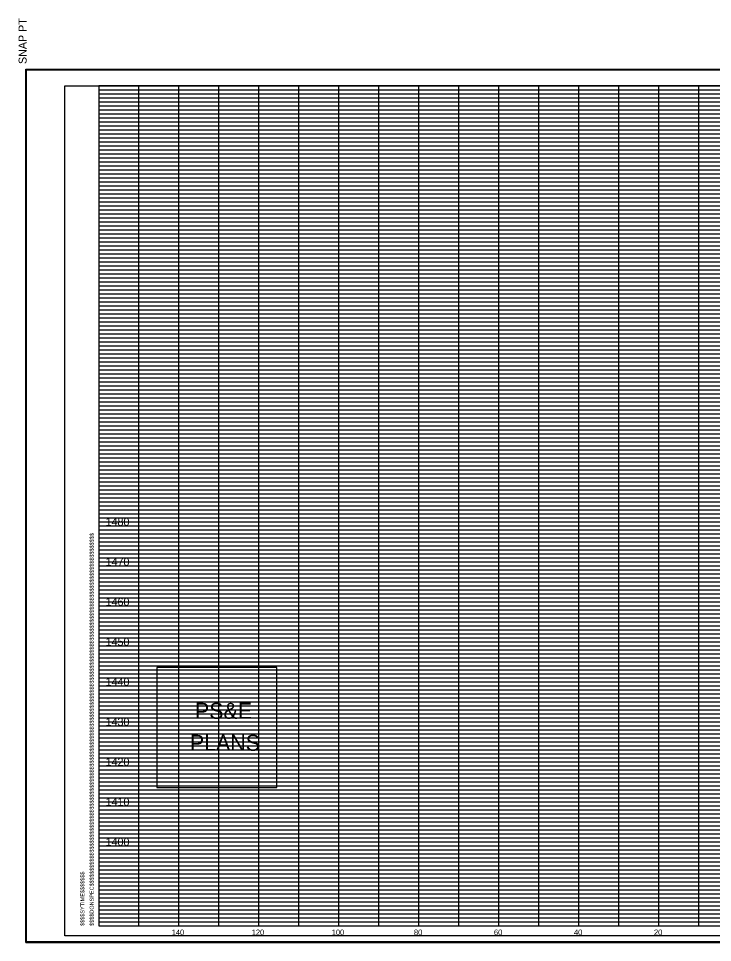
# Model space of a CAD drawing. Extents: x 980 to 2064, y 978 to 2267.
# Drawn here: x 979.9 to 1153.4, y 1515.9 to 1746.8 of the extents above; entities that cross this region are included whole.
import ezdxf

# ---------------------------------------------------------------- set-up
doc = ezdxf.new("R2010")
doc.units = 0
for name, color, linetype in [('Default', 7, 'Continuous'), ('DESIGN - SHEET - Corner Text', 7, 'Continuous'), ('DESIGN - SHEET - Light Grid', 7, 'Continuous'), ('DESIGN - SHEET - Linework', 7, 'Continuous'), ('DESIGN - SHEET - Plot Shape', 7, 'Continuous')]:
    doc.layers.add(name, color=color, linetype=linetype)

# ---------------------------------------------------------------- blocks, each defined once
blk = doc.blocks.new('XSTSHT')
at = {"layer": 'DESIGN - SHEET - Light Grid'}
for p, q in [((0, 20.9), (8, 20.9)), ((0, 20.8), (8, 20.8)), ((8, 20.9), (16, 20.9)), ((8, 20.8), (16, 20.8)), ((0, 20.7), (8, 20.7)), ((0, 20.6), (8, 20.6)), ((8, 20.7), (16, 20.7)), ((8, 20.6), (16, 20.6)), ((0, 20.5), (8, 20.5)), ((0, 20.4), (8, 20.4)), ((8, 20.5), (16, 20.5)), ((8, 20.4), (16, 20.4)), ((0, 20.3), (8, 20.3)), ((0, 20.2), (8, 20.2)), ((0, 20.1), (8, 20.1)), ((8, 20.3), (16, 20.3)), ((8, 20.2), (16, 20.2)), ((8, 20.1), (16, 20.1)), ((0, 19.9), (8, 19.9)), ((8, 19.9), (16, 19.9)), ((0, 19.8), (8, 19.8)), ((0, 19.7), (8, 19.7)), ((8, 19.8), (16, 19.8)), ((8, 19.7), (16, 19.7)), ((0, 19.6), (8, 19.6)), ((0, 19.5), (8, 19.5)), ((0, 19.4), (8, 19.4)), ((8, 19.6), (16, 19.6)), ((8, 19.5), (16, 19.5)), ((8, 19.4), (16, 19.4)), ((0, 19.3), (8, 19.3)), ((0, 19.2), (8, 19.2)), ((8, 19.3), (16, 19.3)), ((8, 19.2), (16, 19.2)), ((0, 19.1), (8, 19.1)), ((8, 19.1), (16, 19.1)), ((0, 18.9), (8, 18.9)), ((0, 18.8), (8, 18.8)), ((8, 18.9), (16, 18.9)), ((8, 18.8), (16, 18.8)), ((0, 18.7), (8, 18.7)), ((0, 18.6), (8, 18.6)), ((0, 18.5), (8, 18.5)), ((8, 18.7), (16, 18.7)), ((8, 18.6), (16, 18.6)), ((8, 18.5), (16, 18.5)), ((0, 18.4), (8, 18.4)), ((0, 18.3), (8, 18.3)), ((8, 18.4), (16, 18.4)), ((8, 18.3), (16, 18.3)), ((0, 18.2), (8, 18.2)), ((0, 18.1), (8, 18.1)), ((8, 18.2), (16, 18.2)), ((8, 18.1), (16, 18.1)), ((0, 17.9), (8, 17.9)), ((0, 17.8), (8, 17.8)), ((8, 17.9), (16, 17.9)), ((8, 17.8), (16, 17.8)), ((0, 17.7), (8, 17.7)), ((0, 17.6), (8, 17.6)), ((8, 17.7), (16, 17.7)), ((8, 17.6), (16, 17.6)), ((0, 17.5), (8, 17.5)), ((0, 17.4), (8, 17.4)), ((8, 17.5), (16, 17.5)), ((8, 17.4), (16, 17.4)), ((0, 17.3), (8, 17.3)), ((0, 17.2), (8, 17.2)), ((0, 17.1), (8, 17.1)), ((8, 17.3), (16, 17.3)), ((8, 17.2), (16, 17.2)), ((8, 17.1), (16, 17.1)), ((0, 16.9), (8, 16.9)), ((8, 16.9), (16, 16.9)), ((0, 16.8), (8, 16.8)), ((0, 16.7), (8, 16.7)), ((8, 16.8), (16, 16.8)), ((8, 16.7), (16, 16.7)), ((0, 16.6), (8, 16.6)), ((0, 16.5), (8, 16.5)), ((0, 16.4), (8, 16.4)), ((8, 16.6), (16, 16.6)), ((8, 16.5), (16, 16.5)), ((8, 16.4), (16, 16.4)), ((0, 16.3), (8, 16.3)), ((0, 16.2), (8, 16.2)), ((8, 16.3), (16, 16.3)), ((8, 16.2), (16, 16.2)), ((0, 16.1), (8, 16.1)), ((8, 16.1), (16, 16.1)), ((0, 15.9), (8, 15.9)), ((0, 15.8), (8, 15.8)), ((8, 15.9), (16, 15.9)), ((8, 15.8), (16, 15.8)), ((0, 15.7), (8, 15.7)), ((0, 15.6), (8, 15.6)), ((0, 15.5), (8, 15.5)), ((8, 15.7), (16, 15.7)), ((8, 15.6), (16, 15.6)), ((8, 15.5), (16, 15.5)), ((0, 15.4), (8, 15.4)), ((0, 15.3), (8, 15.3)), ((8, 15.4), (16, 15.4)), ((8, 15.3), (16, 15.3)), ((0, 15.2), (8, 15.2)), ((0, 15.1), (8, 15.1)), ((8, 15.2), (16, 15.2)), ((8, 15.1), (16, 15.1)), ((0, 14.9), (8, 14.9)), ((0, 14.8), (8, 14.8)), ((8, 14.9), (16, 14.9)), ((8, 14.8), (16, 14.8)), ((0, 14.7), (8, 14.7)), ((0, 14.6), (8, 14.6)), ((8, 14.7), (16, 14.7)), ((8, 14.6), (16, 14.6)), ((0, 14.5), (8, 14.5)), ((0, 14.4), (8, 14.4)), ((8, 14.5), (16, 14.5)), ((8, 14.4), (16, 14.4)), ((0, 14.3), (8, 14.3)), ((0, 14.2), (8, 14.2)), ((0, 14.1), (8, 14.1)), ((8, 14.3), (16, 14.3)), ((8, 14.2), (16, 14.2)), ((8, 14.1), (16, 14.1)), ((0, 13.9), (8, 13.9)), ((8, 13.9), (16, 13.9)), ((0, 13.8), (8, 13.8)), ((0, 13.7), (8, 13.7)), ((8, 13.8), (16, 13.8)), ((8, 13.7), (16, 13.7)), ((0, 13.6), (8, 13.6)), ((0, 13.5), (8, 13.5)), ((0, 13.4), (8, 13.4)), ((8, 13.6), (16, 13.6)), ((8, 13.5), (16, 13.5)), ((8, 13.4), (16, 13.4)), ((0, 13.3), (8, 13.3)), ((0, 13.2), (8, 13.2)), ((8, 13.3), (16, 13.3)), ((8, 13.2), (16, 13.2)), ((0, 13.1), (8, 13.1)), ((8, 13.1), (16, 13.1)), ((0, 12.9), (8, 12.9)), ((0, 12.8), (8, 12.8)), ((8, 12.9), (16, 12.9)), ((8, 12.8), (16, 12.8)), ((0, 12.7), (8, 12.7)), ((0, 12.6), (8, 12.6)), ((0, 12.5), (8, 12.5)), ((8, 12.7), (16, 12.7)), ((8, 12.6), (16, 12.6)), ((8, 12.5), (16, 12.5)), ((0, 12.4), (8, 12.4)), ((0, 12.3), (8, 12.3)), ((8, 12.4), (16, 12.4)), ((8, 12.3), (16, 12.3)), ((0, 12.2), (8, 12.2)), ((0, 12.1), (8, 12.1)), ((8, 12.2), (16, 12.2)), ((8, 12.1), (16, 12.1)), ((0, 11.9), (8, 11.9)), ((0, 11.8), (8, 11.8)), ((8, 11.9), (16, 11.9)), ((8, 11.8), (16, 11.8)), ((0, 11.7), (8, 11.7)), ((0, 11.6), (8, 11.6)), ((8, 11.7), (16, 11.7)), ((8, 11.6), (16, 11.6)), ((0, 11.5), (8, 11.5)), ((0, 11.4), (8, 11.4)), ((8, 11.5), (16, 11.5)), ((8, 11.4), (16, 11.4)), ((0, 11.3), (8, 11.3)), ((0, 11.2), (8, 11.2)), ((0, 11.1), (8, 11.1)), ((8, 11.3), (16, 11.3)), ((8, 11.2), (16, 11.2)), ((8, 11.1), (16, 11.1)), ((0, 10.9), (8, 10.9)), ((8, 10.9), (16, 10.9)), ((0, 10.8), (8, 10.8)), ((0, 10.7), (8, 10.7)), ((8, 10.8), (16, 10.8)), ((8, 10.7), (16, 10.7)), ((0, 10.6), (8, 10.6)), ((0, 10.5), (8, 10.5)), ((0, 10.4), (8, 10.4)), ((8, 10.6), (16, 10.6)), ((8, 10.5), (16, 10.5)), ((8, 10.4), (16, 10.4)), ((0, 10.3), (8, 10.3)), ((0, 10.2), (8, 10.2)), ((8, 10.3), (16, 10.3)), ((8, 10.2), (16, 10.2)), ((0, 10.1), (8, 10.1)), ((8, 10.1), (16, 10.1)), ((0, 9.9), (8, 9.9)), ((0, 9.8), (8, 9.8)), ((0, 9.7), (8, 9.7)), ((8, 9.9), (16, 9.9)), ((8, 9.8), (16, 9.8)), ((8, 9.7), (16, 9.7)), ((0, 9.6), (8, 9.6)), ((0, 9.5), (8, 9.5)), ((8, 9.6), (16, 9.6)), ((8, 9.5), (16, 9.5)), ((0, 9.4), (8, 9.4)), ((0, 9.3), (8, 9.3)), ((8, 9.4), (16, 9.4)), ((8, 9.3), (16, 9.3)), ((0, 9.2), (8, 9.2)), ((0, 9.1), (8, 9.1)), ((8, 9.2), (16, 9.2)), ((8, 9.1), (16, 9.1)), ((0, 8.9), (8, 8.9)), ((0, 8.8), (8, 8.8)), ((8, 8.9), (16, 8.9)), ((8, 8.8), (16, 8.8)), ((0, 8.7), (8, 8.7)), ((0, 8.6), (8, 8.6)), ((8, 8.7), (16, 8.7)), ((8, 8.6), (16, 8.6)), ((0, 8.5), (8, 8.5)), ((0, 8.4), (8, 8.4)), ((8, 8.5), (16, 8.5)), ((8, 8.4), (16, 8.4)), ((0, 8.3), (8, 8.3)), ((0, 8.2), (8, 8.2)), ((0, 8.1), (8, 8.1)), ((8, 8.3), (16, 8.3)), ((8, 8.2), (16, 8.2)), ((8, 8.1), (16, 8.1)), ((0, 7.9), (8, 7.9)), ((8, 7.9), (16, 7.9)), ((0, 7.8), (8, 7.8)), ((0, 7.7), (8, 7.7)), ((8, 7.8), (16, 7.8)), ((8, 7.7), (16, 7.7)), ((0, 7.6), (8, 7.6)), ((0, 7.5), (8, 7.5)), ((0, 7.4), (8, 7.4)), ((8, 7.6), (16, 7.6)), ((8, 7.5), (16, 7.5)), ((8, 7.4), (16, 7.4)), ((0, 7.3), (8, 7.3)), ((0, 7.2), (8, 7.2)), ((8, 7.3), (16, 7.3)), ((8, 7.2), (16, 7.2)), ((0, 7.1), (8, 7.1)), ((8, 7.1), (16, 7.1)), ((0, 6.9), (8, 6.9)), ((0, 6.8), (8, 6.8)), ((0, 6.7), (8, 6.7)), ((8, 6.9), (16, 6.9)), ((8, 6.8), (16, 6.8)), ((8, 6.7), (16, 6.7)), ((0, 6.6), (8, 6.6)), ((0, 6.5), (8, 6.5)), ((8, 6.6), (16, 6.6)), ((8, 6.5), (16, 6.5)), ((0, 6.4), (8, 6.4)), ((0, 6.3), (8, 6.3)), ((8, 6.4), (16, 6.4)), ((8, 6.3), (16, 6.3)), ((0, 6.2), (8, 6.2)), ((0, 6.1), (8, 6.1)), ((8, 6.2), (16, 6.2)), ((8, 6.1), (16, 6.1)), ((0, 5.9), (8, 5.9)), ((0, 5.8), (8, 5.8)), ((8, 5.9), (16, 5.9)), ((8, 5.8), (16, 5.8)), ((0, 5.7), (8, 5.7)), ((0, 5.6), (8, 5.6)), ((8, 5.7), (16, 5.7)), ((8, 5.6), (16, 5.6)), ((0, 5.5), (8, 5.5)), ((0, 5.4), (8, 5.4)), ((8, 5.5), (16, 5.5)), ((8, 5.4), (16, 5.4)), ((0, 5.3), (8, 5.3)), ((0, 5.2), (8, 5.2)), ((0, 5.1), (8, 5.1)), ((8, 5.3), (16, 5.3)), ((8, 5.2), (16, 5.2)), ((8, 5.1), (16, 5.1)), ((0, 4.9), (8, 4.9)), ((8, 4.9), (16, 4.9)), ((0, 4.8), (8, 4.8)), ((0, 4.7), (8, 4.7)), ((8, 4.8), (16, 4.8)), ((8, 4.7), (16, 4.7)), ((0, 4.6), (8, 4.6)), ((0, 4.5), (8, 4.5)), ((0, 4.4), (8, 4.4)), ((8, 4.6), (16, 4.6)), ((8, 4.5), (16, 4.5)), ((8, 4.4), (16, 4.4)), ((0, 4.3), (8, 4.3)), ((0, 4.2), (8, 4.2)), ((8, 4.3), (16, 4.3)), ((8, 4.2), (16, 4.2)), ((0, 4.1), (8, 4.1)), ((8, 4.1), (16, 4.1)), ((0, 3.9), (8, 3.9)), ((0, 3.8), (8, 3.8)), ((0, 3.7), (8, 3.7)), ((8, 3.9), (16, 3.9)), ((8, 3.8), (16, 3.8)), ((8, 3.7), (16, 3.7)), ((0, 3.6), (8, 3.6)), ((0, 3.5), (8, 3.5)), ((8, 3.6), (16, 3.6)), ((8, 3.5), (16, 3.5)), ((0, 3.4), (8, 3.4)), ((0, 3.3), (8, 3.3)), ((8, 3.4), (16, 3.4)), ((8, 3.3), (16, 3.3)), ((0, 3.2), (8, 3.2)), ((0, 3.1), (8, 3.1)), ((8, 3.2), (16, 3.2)), ((8, 3.1), (16, 3.1)), ((0, 2.9), (8, 2.9)), ((0, 2.8), (8, 2.8)), ((8, 2.9), (16, 2.9)), ((8, 2.8), (16, 2.8)), ((0, 2.7), (8, 2.7)), ((0, 2.6), (8, 2.6)), ((8, 2.7), (16, 2.7)), ((8, 2.6), (16, 2.6)), ((0, 2.5), (8, 2.5)), ((0, 2.4), (8, 2.4)), ((8, 2.5), (16, 2.5)), ((8, 2.4), (16, 2.4)), ((0, 2.3), (8, 2.3)), ((0, 2.2), (8, 2.2)), ((0, 2.1), (8, 2.1)), ((8, 2.3), (16, 2.3)), ((8, 2.2), (16, 2.2)), ((8, 2.1), (16, 2.1)), ((0, 1.9), (8, 1.9)), ((8, 1.9), (16, 1.9)), ((0, 1.8), (8, 1.8)), ((0, 1.7), (8, 1.7)), ((8, 1.8), (16, 1.8)), ((8, 1.7), (16, 1.7)), ((0, 1.6), (8, 1.6)), ((0, 1.5), (8, 1.5)), ((0, 1.4), (8, 1.4)), ((8, 1.6), (16, 1.6)), ((8, 1.5), (16, 1.5)), ((8, 1.4), (16, 1.4)), ((0, 1.3), (8, 1.3)), ((0, 1.2), (8, 1.2)), ((8, 1.3), (16, 1.3)), ((8, 1.2), (16, 1.2)), ((0, 1.1), (8, 1.1)), ((8, 1.1), (16, 1.1)), ((0, 0.9), (8, 0.9)), ((0, 0.8), (8, 0.8)), ((0, 0.7), (8, 0.7)), ((8, 0.9), (16, 0.9)), ((8, 0.8), (16, 0.8)), ((8, 0.7), (16, 0.7)), ((0, 0.6), (8, 0.6)), ((0, 0.5), (8, 0.5)), ((8, 0.6), (16, 0.6)), ((8, 0.5), (16, 0.5)), ((0, 0.4), (8, 0.4)), ((0, 0.3), (8, 0.3)), ((8, 0.4), (16, 0.4)), ((8, 0.3), (16, 0.3)), ((0, 0.2), (8, 0.2)), ((0, 0.1), (8, 0.1)), ((8, 0.2), (16, 0.2)), ((8, 0.1), (16, 0.1))]:
    blk.add_line(p, q, dxfattribs=at)
at = {"layer": 'DESIGN - SHEET - Linework'}
for p, q in [((-1.823, -0.414), (-1.823, 21.414)), ((-1.823, 21.414), (32.217, 21.414)), ((1, 0), (1, 21)), ((2, 0), (2, 21)), ((3, 0), (3, 21)), ((4, 0), (4, 21)), ((5, 0), (5, 21)), ((6, 0), (6, 21)), ((7, 0), (7, 21)), ((8, 0), (8, 21)), ((9, 0), (9, 21)), ((10, 0), (10, 21)), ((11, 0), (11, 21)), ((12, 0), (12, 21)), ((13, 0), (13, 21)), ((14, 0), (14, 21)), ((15, 0), (15, 21)), ((0, 20), (28, 20)), ((0, 19), (32, 19)), ((0, 18), (32, 18)), ((0, 17), (32, 17)), ((0, 16), (32, 16)), ((0, 15), (32, 15)), ((0, 14), (32, 14)), ((0, 13), (32, 13)), ((0, 12), (32, 12)), ((0, 11), (32, 11)), ((0, 10), (32, 10)), ((0, 9), (32, 9)), ((0, 8), (32, 8)), ((0, 7), (32, 7)), ((0, 6), (32, 6)), ((0, 5), (32, 5)), ((0, 4), (32, 4)), ((0, 3), (32, 3)), ((0, 2), (32, 2)), ((0, 1), (32, 1)), ((-1.823, -0.414), (32.217, -0.414))]:
    blk.add_line(p, q, dxfattribs=at)
blk.add_lwpolyline([(0, 21), (0, 0), (32, 0), (32, 21), (0, 21)], dxfattribs=at)
at = {"layer": 'DESIGN - SHEET - Plot Shape'}
for points in [[(-1.803, 21.394), (32.197, 21.394), (32.197, -0.394), (-1.803, -0.394)], [(-0.85, 21), (32, 21), (32, -0.25), (-0.85, -0.25)]]:
    blk.add_lwpolyline(points, close=True, dxfattribs=at)
at = {"layer": 'DESIGN - SHEET - Corner Text'}
for s, height, p in [('  SNAP PT', 0.2, (-1.803, 21.394)), ('$$$$DGNSPEC$$$$$$$$$$$$$$$$$$$$$$$$$$$$$$$$$$$$$$$$$$$$$$$$$$$$$$$$$$$$$$$$$$$$$$$$$$$$$$$$$$$$$$$$$$$$$$$$$$$$$$$$$$$$$$$$$$$', 0.100002, (-0.126, 0)), ('$$$$SYTIME$$$$$$$', 0.1, (-0.358, 0))]:
    blk.add_text(s, height=height, rotation=90, dxfattribs=at).set_placement(p)

msp = doc.modelspace()

# ---------------------------------------------------------------- linework, layer by layer
at = {"layer": 'DESIGN - SHEET - Corner Text'}
msp.add_lwpolyline([(1014.54, 1584.59), (1014.54, 1554.59), (1044.54, 1554.59), (1044.54, 1584.59)], close=True, dxfattribs=at)

# ---------------------------------------------------------------- block references
at = {"layer": 'Default', "xscale": 10, "yscale": 10}
msp.add_blockref('XSTSHT', (1000, 1520), dxfattribs=at)

# ---------------------------------------------------------------- texts
at = {"layer": 'Default'}
for s, height, p in [('     1480     ', 2, (998.01, 1620)), ('     1470     ', 2, (998.01, 1610)), ('     1460     ', 2, (998.01, 1600)), ('     1450     ', 2, (998.01, 1590)), ('     1440     ', 2, (998.01, 1580)), ('     1430     ', 2, (998.01, 1570)), ('     1420     ', 2, (998.01, 1560)), ('     1410     ', 2, (998.01, 1550)), ('     1400     ', 2, (998.01, 1540)), ('     140     ', 1.4, (1015.65, 1517.7)), ('     120     ', 1.4, (1035.65, 1517.7)), ('     100     ', 1.4, (1055.65, 1517.7)), ('     80     ', 1.4, (1076.2, 1517.7)), ('     60     ', 1.4, (1096.2, 1517.7)), ('     40     ', 1.4, (1116.2, 1517.7)), ('     20     ', 1.4, (1136.2, 1517.7))]:
    msp.add_text(s, height=height, dxfattribs=at).set_placement(p)
at = {"layer": 'DESIGN - SHEET - Corner Text'}
for s, p in [('PS&E', (1024.06, 1571.77)), ('PLANS', (1022.78, 1563.77))]:
    msp.add_text(s, height=4, dxfattribs=at).set_placement(p)

doc.saveas('drawing.dxf')
